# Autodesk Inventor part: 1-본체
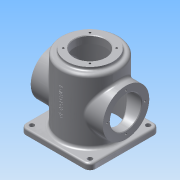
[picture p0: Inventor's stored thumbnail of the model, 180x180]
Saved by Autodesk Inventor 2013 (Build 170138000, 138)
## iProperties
Created: 2015-10
Part Number: 1-본체
Material: 알루미늄 6061
Document SubType Name: Modeling
Designer: semtle
Density: 2.71 g/cm^3
Mass: 993.411 g
Surface Area: 1041.55 cm^2
Volume: 366.572 cm^3
Author: semtle
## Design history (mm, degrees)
sketch "스케치1"
  geometry: L1 (-60, 60)-(60, 60); L2 (60, 60)-(60, -60); L3 (60, -60)-(-60, -60); L4 (-60, -60)-(-60, 60); C1 r 4 at (-50, 50); C2 r 4 at (50, 50); C3 r 4 at (50, -50); C4 r 4 at (-50, -50); 3 further points
  constraints: 8 end point, 4 centre point, 3 equal radius, 3 horizontal alignment, 3 vertical alignment, 2 midpoint, 2 parallel, 1 horizontal, 1 perpendicular
  dimensions: "d0" = 120 distance of L1.start L1.end; "d2" = 120 distance of L1.end L2.end; "d3" = 100 distance of C2.centre C1.centre; "d4" = 50 horizontal distance of C2.centre point (0, 0); "d5" = 100 distance of C3.centre C2.centre; "d6" = 50 horizontal distance of C3.centre point (0, 0); "d7" = 8 diameter of C2
extrude "돌출1" new body sketch "스케치1" distance "d8" = 10; taper "d9" = 0 deg
sketch "스케치2"
  geometry: C1 r 50 at (0, 0); 1 further point
  constraints: 1 centre point, 1 coincident
  dimensions: "d10" = 100 diameter of C1
extrude "돌출2" join sketch "스케치2" distance "d12" = 110; taper "d13" = 0 deg
sketch "스케치4"
  geometry: C1 r 45 at (0, 0); 1 further point
  constraints: 1 centre point, 1 coincident
  dimensions: "d16" = 90 diameter of C1
extrude "돌출4" cut sketch "스케치4" distance "d19" = 112; taper "d20" = 0 deg
sketch "스케치5"
  geometry: C1 r 50 at (0, 0) reference; C2 r 40 at (0, 0)
  constraints: 1 centre point, 1 coincident
  dimensions: "d21" = 80 diameter of C2
extrude "돌출5" join sketch "스케치5" distance "d23" = 5; taper "d24" = 0 deg
sketch "스케치6"
  geometry: C1 r 40 at (0, 0) reference; C2 r 27 at (0, 0)
  constraints: 1 centre point, 1 coincident
  dimensions: "d25" = 54 diameter of C2
extrude "돌출6" cut sketch "스케치6" distance "d27" = 13; taper "d28" = 0 deg
node "작업 평면1"
sketch "스케치7"
  geometry: L1 (50, 110)-(-50, 110) reference; L2 (-50, 0)-(50, 0) reference; L3 (45, -10)-(-45, -10) reference; 3 further points
  constraints: 1 midpoint, 1 vertical alignment, 1 other
  dimensions: "d29" = 70 distance from line of point (0, 60) L3
feature "엠보싱1" sketch "스케치7" dims "d0" = 120, "d2" = 120, "d30" = 0.5, "d31" = 0
sketch "스케치8"
  geometry: L1 (60, 60)-(-60, 60) reference; L2 (-60, 60)-(-60, -60) reference; L3 (-60, -60)-(60, -60) reference; L4 (60, -60)-(60, 60) reference; C1 r 27 at (0, 0) reference; C2 r 50 at (0, 0) reference; C3 r 4 at (-50, -50) reference; C4 r 4 at (50, -50) reference; C5 r 4 at (50, 50) reference; C6 r 4 at (-50, 50) reference; A1 r 32.5 centre (0, 0) between (-22.981, 22.981) and (22.981, 22.981); 2 further points
  constraints: 4 point on circle, 2 horizontal alignment, 2 vertical alignment, 1 centre point, 1 coincident
  dimensions: "d32" = 65 diameter of A1; "d34" = 90 deg dimension on C1.centre A1.end A1.start
hole "구멍1" sketch "스케치8" at (-22.981, 22.981), (22.981, 22.981), (22.981, -22.981), (-22.981, -22.981) diameter "d36" = 3.242; stored, may be unused: countersink angle "d40" = 90 deg, drill point angle "d42" = 118 deg; dims "d37" = 8, "d38" = 4, "d39" = 2, "d41" = 10
chamfer "모따기1" distance "d61" = 3; stored, may be unused: second distance "d62" = 2, angle "d63" = 45 deg
chamfer "모따기2" distance "d64" = 1; stored, may be unused: second distance "d65" = 2, angle "d66" = 45 deg
fillet "모깎기1" dims "d67" = 5
fillet "모깎기2" dims "d68" = 10
fillet "모깎기3" dims "d69" = 5
fillet "모깎기4" dims "d70" = 3
fillet "모깎기5" dims "d71" = 3
fillet "모깎기6" dims "d72" = 3
node "작업 평면3"
sketch "스케치12"
  geometry: C1 r 40 at (0, 60); 1 further point
  constraints: 1 centre point, 1 vertical alignment
  dimensions: "d75" = 60 distance of C1.centre point (0, 0); "d76" = 80 diameter of C1
extrude "돌출9" join sketch "스케치12" stored distance "d77" = 10; taper "d78" = 0 deg
sketch "스케치13"
  geometry: C1 r 40 at (0, 0) reference; C2 r 27 at (0, 0); 1 further point
  constraints: 1 centre point, 1 coincident
  dimensions: "d79" = 54 diameter of C2
extrude "돌출10" cut sketch "스케치13" stored distance "d81" = 10; taper "d82" = 0 deg
sketch "스케치14"
  geometry: C1 r 27 at (0, 0) reference; C2 r 40 at (0, 0) reference; A1 r 32.5 centre (0, 0) between (-32.5, 0) and (32.5, 0); 3 further points
  constraints: 4 point on circle, 2 horizontal alignment, 2 vertical alignment, 1 centre point, 1 coincident
  dimensions: "d83" = 65 diameter of A1
hole "구멍3" sketch "스케치14" at (-32.5, 0), (32.5, 0), (0, 32.5), (0, -32.5) diameter "d85" = 3.242; stored, may be unused: countersink angle "d89" = 90 deg, drill point angle "d91" = 118 deg; dims "d86" = 8, "d87" = 4, "d88" = 2, "d90" = 10
fillet "모깎기7" dims "d92" = 5
fillet "모깎기8" dims "d93" = 3
chamfer "모따기3" distance "d94" = 1; stored, may be unused: second distance "d95" = 2, angle "d96" = 45 deg
node "솔리드1"
mirror "대칭2"
node "투영된 루프1"
node "투영된 루프2"
other parameters: "d74" = 62
